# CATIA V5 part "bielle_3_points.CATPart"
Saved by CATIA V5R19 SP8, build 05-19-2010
Part number: bielle_3_points
Bounding box of the stored display mesh (mm): x -5 to 5, y -84.862 to 84.862, z -9.92 to 85
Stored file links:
  C:\Users\ThinkMotion\Desktop\EU_thinkMotion\iao\IAO_MMS_Groupe3\avercruysse\IAO_vercruysse\IAO_vercruysse\bielle_3_points.CATPart
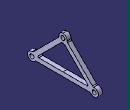
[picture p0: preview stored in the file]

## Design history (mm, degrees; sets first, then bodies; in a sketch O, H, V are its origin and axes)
Body1 (main body)
  Sketch1 on yz-plane, origin (0, 0, 0), H (0, 1, 0), V (0, 0, 1)
    construction line L1 (0, -123.6331) -> (0, 200.5778)
    point P1 (0, -123.6331)
    arc A1 centre (75, 0) radius 10 from (66.3397, -5) to (72.4118, 9.6593) ccw
    point P3 (75, 0)
    circle A2 centre (75, 0) radius 5
    point P4 (0, 75)
    arc A3 centre (0, 75) radius 5 from (0, 70) to (0, 80) ccw
    axis line L2 (75, 0) -> (0, 75)
    reference intersected line E1 through (0, 0) direction (-1, 0) from xy-plane
    point P5 (0, 80)
    point P6 (0, 70)
    point P7 (0, 85)
    line L3 (72.4118, 9.6593) -> (9.6593, 72.4118)
    point P8 (72.4118, 9.6593)
    point P9 (9.6593, 72.4118)
    line L4 (62.9289, 5) -> (0, 67.9289)
    line L5 (62.9289, 5) -> (0, 5)
    point P10 (0, 5)
    line L6 (66.3397, -5) -> (0, -5)
    point P11 (66.3397, -5)
    point P12 (0, -5)
    reference intersected line E2 through (0, 0) direction (-1, 0) from xy-plane
    arc A4 centre (0, 75) radius 10 from (9.6593, 72.4118) to (0, 85) ccw
    point P13 (62.9289, 5)
    point P14 (0, 67.9289)
    circle A5 centre (-75, 0) radius 5
    point P16 (-72.4118, 9.6593)
    point P17 (-66.3397, -5)
    arc A6 centre (-75, 0) radius 10 from (-66.3397, -5) to (-72.4118, 9.6593) cw
    point P18 (0, -5)
    line L7 (-66.3397, -5) -> (0, -5)
    point P19 (0, 5)
    point P20 (-62.9289, 5)
    line L8 (-62.9289, 5) -> (0, 5)
    point P21 (0, 67.9289)
    line L9 (-62.9289, 5) -> (0, 67.9289)
    point P22 (-9.6593, 72.4118)
    line L10 (-72.4118, 9.6593) -> (-9.6593, 72.4118)
    point P23 (0, 85)
    arc A7 centre (0, 75) radius 10 from (-9.6593, 72.4118) to (0, 85) cw
    point P25 (0, 80)
    point P26 (0, 70)
    arc A8 centre (0, 75) radius 5 from (0, 70) to (0, 80) cw
    distance L1 P3 = 75
    radius A1 = 10
    radius A2 = 5
    angle E1 L2 = 45
    radius A3 = 5
    distance L2 L3 = 5
    distance L4 L3 = 10
    distance L6 L5 = 10
    distance E2 L6 = 5
    radius A4 = 10
    coincidence: P1 V, P3 H, P4 L1, L1 P5, L1 P6, L1 P7, P10 L1, P12 L1, L1 P14, P5 P25, P6 P26, P7 P23, P10 P19, P12 P18, P14 P21
    vertical: L1 V
    parallelism: L4 L2
    horizontal: L5 H, L6 H
    symmetry: A2 A5 L1, P8 P16 L1, P11 P17 L1, A1 A6 L1, P12 P18 L1, L6 L7 L1, P10 P19 L1, P13 P20 L1, L5 L8 L1, P14 P21 L1, L4 L9 L1, P9 P22 L1, L3 L10 L1, P7 P23 L1, A4 A7 L1, P5 P25 L1, P6 P26 L1, A3 A8 L1
  Pad1: profile Sketch1, direction (1, 0, 0), length 5, opposite side length 5
  Fillet1: radius 2, on edge [face of Pad1 from Sketch1.L9 | face of Pad1 from Sketch1.L8]; edge [face of Pad1 from Sketch1.L5 | face of Pad1 from Sketch1.L4]
  Fillet2: radius 8, on edge [face of Pad1 from Sketch1.L4 | face of Pad1 from Sketch1.L9]
  Fillet3: radius 4, on edge [face of Pad1 from Sketch1.A6 | face of Pad1 from Sketch1.L10]; edge [face of Pad1 from Sketch1.L10 | face of Pad1 from Sketch1.A7]; edge [face of Pad1 from Sketch1.A4 | face of Pad1 from Sketch1.L3]; edge [face of Pad1 from Sketch1.L3 | face of Pad1 from Sketch1.A1]; edge [face of Pad1 from Sketch1.A1 | face of Pad1 from Sketch1.L6]; edge [face of Pad1 from Sketch1.L7 | face of Pad1 from Sketch1.A6]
